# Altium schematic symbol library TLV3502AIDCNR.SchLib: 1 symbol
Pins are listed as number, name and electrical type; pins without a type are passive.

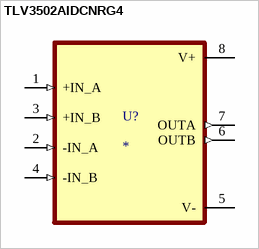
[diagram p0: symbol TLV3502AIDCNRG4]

## TLV3502AIDCNRG4
designator U?
4.5ns Rail-to-Rail Comparator 8-SOT-23 -40 to 125; MP: TLV3502AIDCNRG4; MF: Texas Instruments
footprint TLV3502AIDCNR
pins: 1 +IN_A (in), 2 -IN_A (in), 3 +IN_B (in), 4 -IN_B (in), 5 V- (power), 6 OUTB (out), 7 OUTA (out), 8 V+ (power)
